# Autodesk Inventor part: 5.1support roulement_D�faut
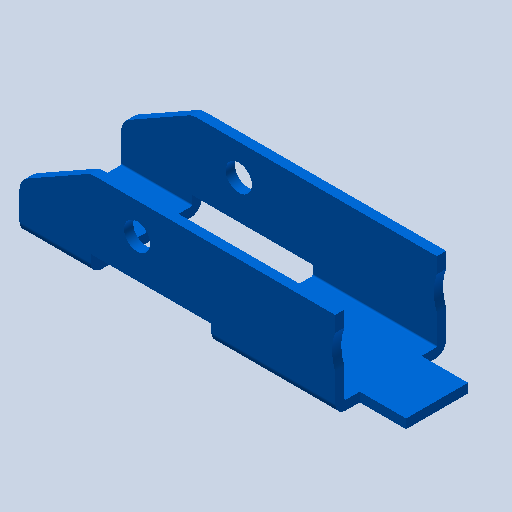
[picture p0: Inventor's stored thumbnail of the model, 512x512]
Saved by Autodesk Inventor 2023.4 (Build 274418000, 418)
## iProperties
Created: 2011-01
Part Number: 5.1support roulement_D�faut
Document SubType Name: Modeling
Designer: eric
Density: 1 g/cm^3
Mass: 20.8377 g
Surface Area: 157.409 cm^2
Volume: 20.8377 cm^3
Material: Générique
Appearance: 0,128,255_1
Author: eric
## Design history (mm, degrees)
feature "Base1"
node "Corps solides"
node "Corps surfaciques"
node "Solide1"
